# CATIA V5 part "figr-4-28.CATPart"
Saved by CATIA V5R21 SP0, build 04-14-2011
Part number: Part1
Bounding box of the stored display mesh (mm): x 0 to 40, y -49.816 to 150, z -49.907 to 49.907
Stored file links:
  D:\CATIA V5R21 E-RESOURCES\CATIA-V5R21\catia-v5r21-prt\c04-catia-v5r20-prt\catia-v5r21-figr-4-27.CATPart
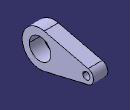
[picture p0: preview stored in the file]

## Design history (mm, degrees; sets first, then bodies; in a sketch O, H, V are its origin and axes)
Body1 (main body)
  Sketch1 on yz-plane, origin (0, 0, 0), H (0, 1, 0), V (0, 0, 1)
    arc A1 centre (0, 0) radius 50 from (11.5385, 48.6504) to (11.5385, -48.6504) ccw
    arc A2 centre (130, 0) radius 20 from (134.6154, -19.4602) to (134.6154, 19.4602) ccw
    point P1 (130, 0)
    line L1 (134.6154, 19.4602) -> (11.5385, 48.6504)
    line L2 (134.6154, -19.4602) -> (11.5385, -48.6504)
    circle A3 centre (0, 0) radius 30
    circle A4 centre (130, 0) radius 10
    point P6 (120, 0)
    coincidence: P1 H, A4 P6, P6 H
    tangency: L1 A2, L1 A1, L2 A2, L2 A1
  Pad1: profile Sketch1, direction (1, 0, 0), length 40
